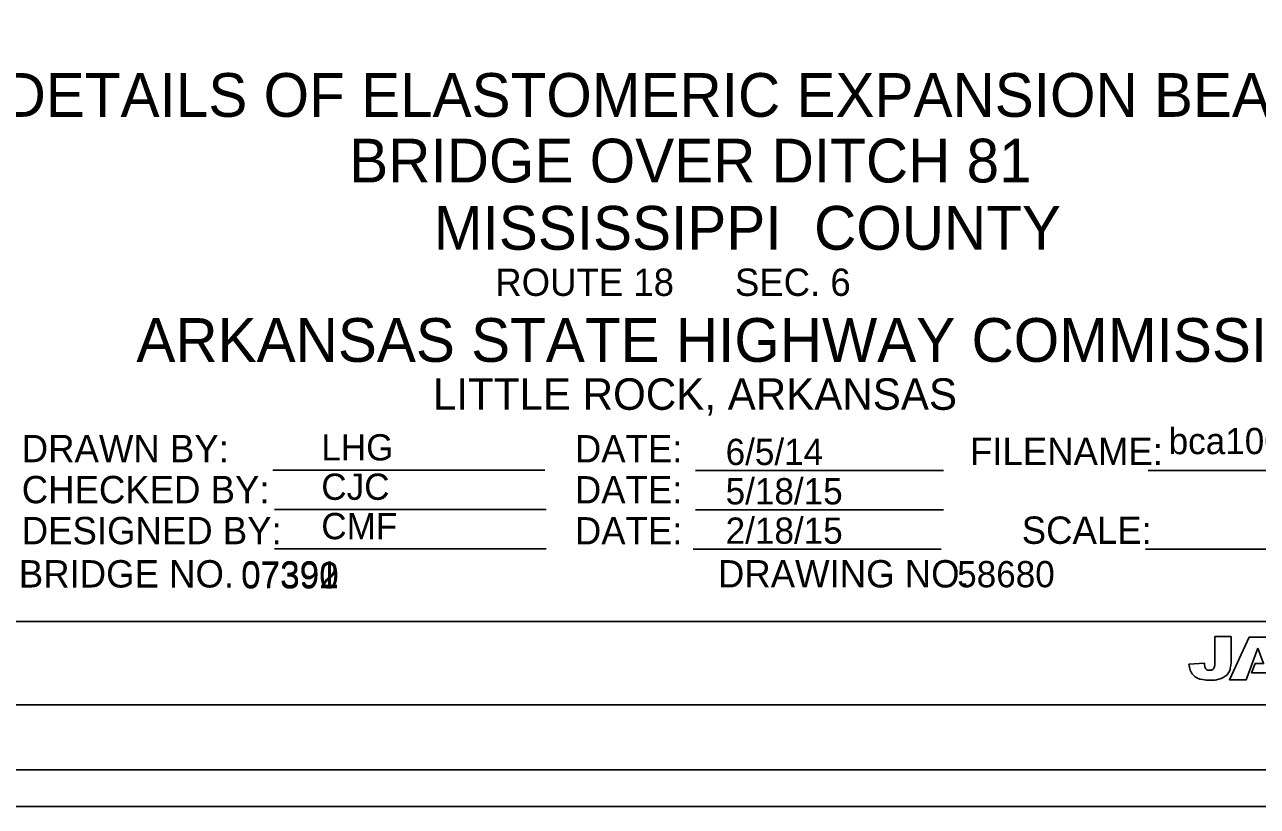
# Model space of a CAD drawing. Extents: x -194 to 226, y 505 to 725.
# Drawn here: x 76.6 to 132.9, y 505.4 to 541.1 of the extents above; entities that cross this region are included whole.
import ezdxf

# ---------------------------------------------------------------- set-up
doc = ezdxf.new("R2010")
doc.units = 0
for name, color, linetype in [('border', 7, 'Continuous'), ('Border 2660-Hwy18 - Level 62', 7, 'Continuous'), ('Border 2660-Hwy18 - Level 63', 7, 'Continuous'), ('Border 2660-Hwy18 - Text', 7, 'Continuous'), ('Border 2660-Hwy18 - Title Text', 7, 'Continuous'), ('Bridge No BLFR', 7, 'Continuous'), ('Bridge No BLO', 7, 'Continuous'), ('Bridge No Ditch 81', 7, 'Continuous'), ('Level 62 PDF', 7, 'Continuous'), ('Text', 7, 'Continuous'), ('Title Block Text', 7, 'Continuous'), ('Title Text', 7, 'Continuous')]:
    doc.layers.add(name, color=color, linetype=linetype)

msp = doc.modelspace()

# ---------------------------------------------------------------- linework, layer by layer
at = {"layer": 'border'}
for p, q in [((87.907, 520.772), (100.339, 520.772)), ((107.239, 520.76), (118.579, 520.76)), ((127.939, 520.76), (141.3, 520.76)), ((87.979, 518.972), (100.411, 518.972)), ((107.239, 518.96), (118.579, 518.96)), ((87.979, 517.172), (100.411, 517.172)), ((107.131, 517.16), (118.471, 517.16)), ((127.815, 517.16), (139.471, 517.16)), ((143.779, 513.86), (-176.332, 513.86))]:
    msp.add_line(p, q, dxfattribs=at)
for points in [[(131.728, 512.064), (131.728, 513.165), (130.987, 513.165), (130.987, 511.958)], [(132.956, 512.638), (133.216, 511.934), (132.829, 511.934), (132.668, 511.51), (133.37, 511.51), (133.488, 511.186), (134.263, 511.186), (133.367, 513.147), (132.56, 513.147), (131.661, 511.186), (132.417, 511.186), (132.956, 512.638)], [(130.512, 511.949), (129.804, 511.912)]]:
    msp.add_lwpolyline(points, dxfattribs=at)
for centre, radius, start, end in [((131.024, 512.008), 1.226, 184.5698, 198.1069), ((131.115, 511.928), 0.602, 178.2556, 191.4961), ((130.195, 511.955), 0.792, 349.1575, 360), ((130.492, 512.023), 1.237, 351.3706, 1.8291), ((130.359, 511.791), 0.527, 198.1069, 225.9799), ((130.547, 511.985), 0.797, 225.9799, 261.0714), ((130.796, 511.863), 0.277, 191.4961, 218.7511), ((130.708, 511.793), 0.164, 218.7511, 257.488), ((130.747, 511.97), 0.345, 257.488, 275.7834), ((130.756, 511.882), 0.257, 275.7834, 301.6926), ((130.827, 511.768), 0.122, 301.6926, 325.4171), ((130.693, 511.86), 0.285, 325.4171, 349.1575), ((130.919, 512.109), 0.931, 279.1616, 305.8646), ((131.122, 511.829), 0.585, 305.8646, 338.7843), ((131.175, 511.808), 0.527, 338.7843, 350.0951), ((126.285, 512.662), 5.492, 350.0951, 351.3706), ((130.802, 513.61), 2.441, 261.0714, 269.9405), ((130.801, 512.839), 1.671, 269.9405, 279.1616)]:
    msp.add_arc(centre, radius, start, end, dxfattribs=at)
at = {"layer": 'Border 2660-Hwy18 - Level 62'}
msp.add_lwpolyline([(-192.533, 725.169), (148.651, 725.169), (148.651, 507.073), (-192.533, 507.073)], close=True, dxfattribs=at)
at = {"layer": 'Border 2660-Hwy18 - Level 63'}
msp.add_lwpolyline([(-193.644, 723.74), (146.351, 723.74), (146.351, 510.044), (-193.644, 510.044)], close=True, dxfattribs=at)
at = {"layer": 'Level 62 PDF'}
msp.add_lwpolyline([(-190.033, 723.503), (151.151, 723.503), (151.151, 505.407), (-190.033, 505.407)], close=True, dxfattribs=at)

# ---------------------------------------------------------------- texts
at = {"layer": 'Border 2660-Hwy18 - Text'}
for s, p in [('DRAWN BY:', (76.423, 521.137)), ('DATE:', (101.719, 521.127)), ('FILENAME:', (119.789, 521.005)), ('CHECKED BY:', (76.423, 519.262)), ('DATE:', (101.719, 519.252)), ('DESIGNED BY:', (76.423, 517.387)), ('SCALE:', (122.155, 517.405)), ('DATE:', (101.719, 517.377)), ('BRIDGE NO.', (76.288, 515.41)), ('DRAWING NO.', (108.262, 515.412))]:
    msp.add_text(s, height=1.25, dxfattribs=at).set_placement(p)
at = {"layer": 'Border 2660-Hwy18 - Title Text'}
for s, height, p in [('MISSISSIPPI  COUNTY', 1.99999, (95.269, 530.85)), ('ROUTE 18      SEC. 6', 1.25, (98.078, 528.739)), ('ARKANSAS STATE HIGHWAY COMMISSION', 1.99999, (81.666, 525.724)), ('LITTLE ROCK, ARKANSAS', 1.44, (95.227, 523.532))]:
    msp.add_text(s, height=height, dxfattribs=at).set_placement(p)
at = {"layer": 'Bridge No BLFR'}
msp.add_text('07392', height=1.2, dxfattribs=at).set_placement((86.457, 515.366))
at = {"layer": 'Bridge No BLO'}
msp.add_text('07391', height=1.2, dxfattribs=at).set_placement((86.457, 515.411))
at = {"layer": 'Bridge No Ditch 81'}
msp.add_text('07390', height=1.2, dxfattribs=at).set_placement((86.457, 515.366))
at = {"layer": 'Text'}
for s, p in [('LHG', (90.122, 521.217)), ('6/5/14', (108.614, 521.009)), ('CJC', (90.122, 519.417)), ('5/18/15', (108.614, 519.209)), ('CMF', (90.122, 517.617)), ('2/18/15', (108.614, 517.409))]:
    msp.add_text(s, height=1.2, dxfattribs=at).set_placement(p)
at = {"layer": 'Title Block Text'}
for s, p in [('bca1002x1_ex1.dgn', (128.875, 521.505)), ('58680', (119.203, 515.42))]:
    msp.add_text(s, height=1.2, dxfattribs=at).set_placement(p)
at = {"layer": 'Title Text'}
for s, p in [('DETAILS OF ELASTOMERIC EXPANSION BEARINGS ', (75.593, 536.924)), ('BRIDGE OVER DITCH 81', (91.4, 533.924))]:
    msp.add_text(s, height=1.99999, dxfattribs=at).set_placement(p)

doc.saveas('drawing.dxf')
